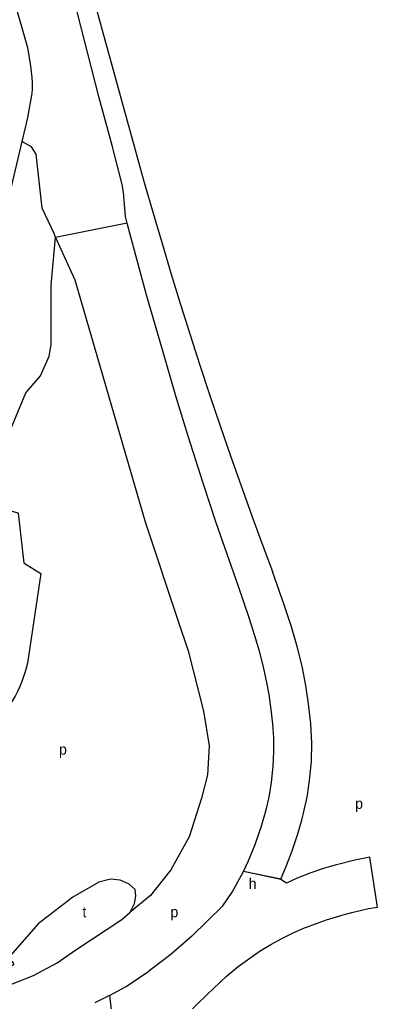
# Model space of a CAD drawing. Extents: x 161093 to 163177, y 379000 to 380904.
# Drawn here: x 162879.5 to 163013.9, y 379600.5 to 379969.3 of the extents above; entities that cross this region are included whole.
import ezdxf

# ---------------------------------------------------------------- set-up
doc = ezdxf.new("R2010")
doc.units = 0
for name, color, linetype in [('BLT_Basislijn', 7, 'Continuous'), ('BLT_Centroide', 7, 'Continuous'), ('BLT_Vlakafsluiter', 7, 'Continuous')]:
    doc.layers.add(name, color=color, linetype=linetype)

msp = doc.modelspace()

# ---------------------------------------------------------------- linework, layer by layer
at = {"layer": 'BLT_Basislijn'}
for p, q in [((162862.81, 380027.11), (162882.43, 379958.85)), ((162909.42, 379940.01), (162889.3, 380018.27)), ((162905.9, 379981.98), (162926.34, 379908.19)), ((162881.65, 379929.27), (162880.31, 379923.61)), ((162880.31, 379923.61), (162865.43, 379860.9)), ((162881.17, 379765.13), (162887.51, 379761.28)), ((162887.51, 379761.28), (162882.41, 379727.61))]:
    msp.add_line(p, q, dxfattribs=at)
for points in [[(162882.43, 379958.85), (162883.6, 379951.9), (162883.87, 379949.76), (162884.05, 379947.62), (162884.14, 379945.48), (162884.15, 379943.33), (162884.08, 379941.56)], [(162884.08, 379941.56), (162882.4, 379932.61), (162881.9, 379930.29), (162881.65, 379929.27)], [(162919.94, 379892.84), (162919.27, 379895.38), (162918.58, 379904.59), (162918.06, 379907.38), (162914.25, 379922.03), (162909.42, 379940.01)], [(162892.91, 379887.54), (162892.47, 379889.01), (162887.9, 379898.56), (162885.67, 379918.78), (162883.92, 379921.58), (162880.31, 379923.61)], [(162926.34, 379908.19), (162929.63, 379896.68), (162933, 379885.2), (162936.45, 379873.73), (162939.97, 379862.29), (162943.58, 379850.87), (162947.25, 379839.48), (162951.01, 379828.11), (162954.83, 379816.77), (162958.74, 379805.45), (162962.72, 379794.16), (162966.77, 379782.9), (162970.91, 379771.66), (162974.5, 379762.08)], [(162963.61, 379649.31), (162965.42, 379653.1), (162967.99, 379659.44), (162969.77, 379664.59), (162970.26, 379666.01), (162972.14, 379672.44), (162973.29, 379677.21), (162974.1, 379682.76), (162974.74, 379688.9), (162974.98, 379694.34), (162974.98, 379699.57), (162974.61, 379704.81), (162974.02, 379710.17), (162973.24, 379715.78), (162972.39, 379720.36), (162971.08, 379726.25), (162969.64, 379732.03), (162967.94, 379737.91), (162965.75, 379744.67), (162961.57, 379756.78), (162953.38, 379780.34), (162948.48, 379795.2), (162942.82, 379812.85), (162938.33, 379827.48), (162933.14, 379845.25), (162927.3, 379865.47), (162921.06, 379888.57), (162919.94, 379892.84)], [(162881.17, 379765.13), (162879.06, 379783.98), (162867.41, 379786.96), (162867.36, 379788.32), (162874.56, 379811.65), (162881.85, 379829.08), (162887.3, 379835.5), (162890.61, 379842.93), (162891.32, 379847.3), (162891.32, 379869.55), (162892.91, 379887.54)], [(162892.91, 379887.54), (162900.23, 379871.56), (162926.68, 379780.68), (162938.98, 379743.78), (162942.78, 379732.23), (162948.56, 379709.49), (162950.69, 379696.5), (162950.06, 379685.62), (162947.87, 379676.86), (162943.23, 379662.29), (162936.25, 379649.91), (162928.66, 379640.28), (162921.01, 379634.07)], [(162977.67, 379646.41), (162979.74, 379651.53), (162981.95, 379657.14), (162983.91, 379663.07), (162985.59, 379668.62), (162987.25, 379676.07), (162987.69, 379678.04), (162988.47, 379683.55), (162989.15, 379690.65), (162989.26, 379697.68), (162988.9, 379704.73), (162988.07, 379712.35), (162987.04, 379719.25), (162985.67, 379726.41), (162983.79, 379733.84), (162981.71, 379741.21), (162979.06, 379749.1), (162974.5, 379762.08)], [(162882.41, 379727.61), (162881.97, 379725.76), (162881.46, 379723.94), (162880.87, 379722.14), (162880.21, 379720.36), (162879.47, 379718.62), (162878.65, 379716.91), (162877.77, 379715.23), (162876.82, 379713.6), (162875.8, 379712), (162874.71, 379710.45), (162873.56, 379708.95), (162872.34, 379707.49), (162871.12, 379706.15)], [(163011.17, 379654.74), (163005.47, 379653.59), (162998.07, 379651.74), (162994.08, 379650.59), (162988.96, 379648.79), (162983.84, 379646.78), (162979.78, 379644.95)], [(162921.01, 379634.07), (162922.67, 379637.34), (162923.15, 379640.15), (162922.94, 379642.53), (162920.62, 379644.53), (162917.29, 379646.02), (162913.67, 379646.48), (162909.23, 379645.28), (162899.44, 379639.68), (162886.47, 379629.66), (162875.15, 379616.76), (162877.07, 379615.14), (162877.23, 379614.29), (162875.26, 379612.99), (162868, 379610.95), (162860.1, 379609.31), (162840.01, 379605.63), (162837.51, 379605.17), (162836.47, 379603.82), (162836.05, 379602.65)], [(162955.87, 379636.47), (162959.39, 379641.57), (162963.58, 379649.26)], [(162963.58, 379649.26), (162963.61, 379649.31)], [(162977.65, 379646.36), (162977.67, 379646.41)], [(162979.78, 379644.95), (162977.65, 379646.36)], [(162955.87, 379636.47), (162944.18, 379625.04), (162936.25, 379618.09), (162927.99, 379611.91)], [(162942.4, 379595.2), (162943.88, 379597.01), (162945.86, 379599.14), (162949.92, 379603.11), (162957.13, 379609.88), (162961.65, 379613.66), (162966.92, 379617.44), (162969.93, 379619.51), (162973.84, 379621.89), (162978.09, 379624.19), (162981.99, 379626.11), (162985.88, 379627.85), (162992.05, 379630.2), (162994.79, 379631.15), (163001.11, 379633.05), (163004.33, 379633.9), (163010.66, 379635.37), (163013.94, 379635.92)], [(162838.11, 379598), (162840.52, 379598.17), (162860.47, 379602.49), (162873.9, 379605.94), (162884.74, 379610.24), (162893.56, 379614.97), (162900.59, 379619.86), (162917.85, 379631.23), (162921.01, 379634.07)], [(162913.28, 379602.7), (162919.47, 379606.12), (162927.99, 379611.91)], [(162913.23, 379602.68), (162907.79, 379600)], [(162913.28, 379602.7), (162913.23, 379602.68)]]:
    msp.add_lwpolyline(points, dxfattribs=at)
at = {"layer": 'BLT_Vlakafsluiter'}
for p, q in [((162919.94, 379892.84), (162892.91, 379887.54)), ((163013.94, 379635.92), (163011.17, 379654.74)), ((162977.65, 379646.36), (162963.58, 379649.26)), ((162977.67, 379646.41), (162963.61, 379649.31)), ((162913.23, 379602.68), (162915.1, 379587.15)), ((162913.28, 379602.7), (162915.15, 379587.17))]:
    msp.add_line(p, q, dxfattribs=at)

# ---------------------------------------------------------------- texts
at = {"layer": 'BLT_Centroide'}
for s, p in [('p', (162894.26, 379693.21)), ('p', (163005.57, 379672.85)), ('h', (162965.57, 379642.77)), ('t', (162903.08, 379632.12)), ('p', (162936.14, 379632.12))]:
    msp.add_text(s, height=4, dxfattribs=at).set_placement(p)

doc.saveas('drawing.dxf')
